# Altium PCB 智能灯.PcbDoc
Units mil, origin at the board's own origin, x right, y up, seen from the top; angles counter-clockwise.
Board outline 3937.01 x 3937.01 mil, 2 copper layers (Top Layer, Bottom Layer); 70 components, 42 nets, 334 pads, 4 vias.
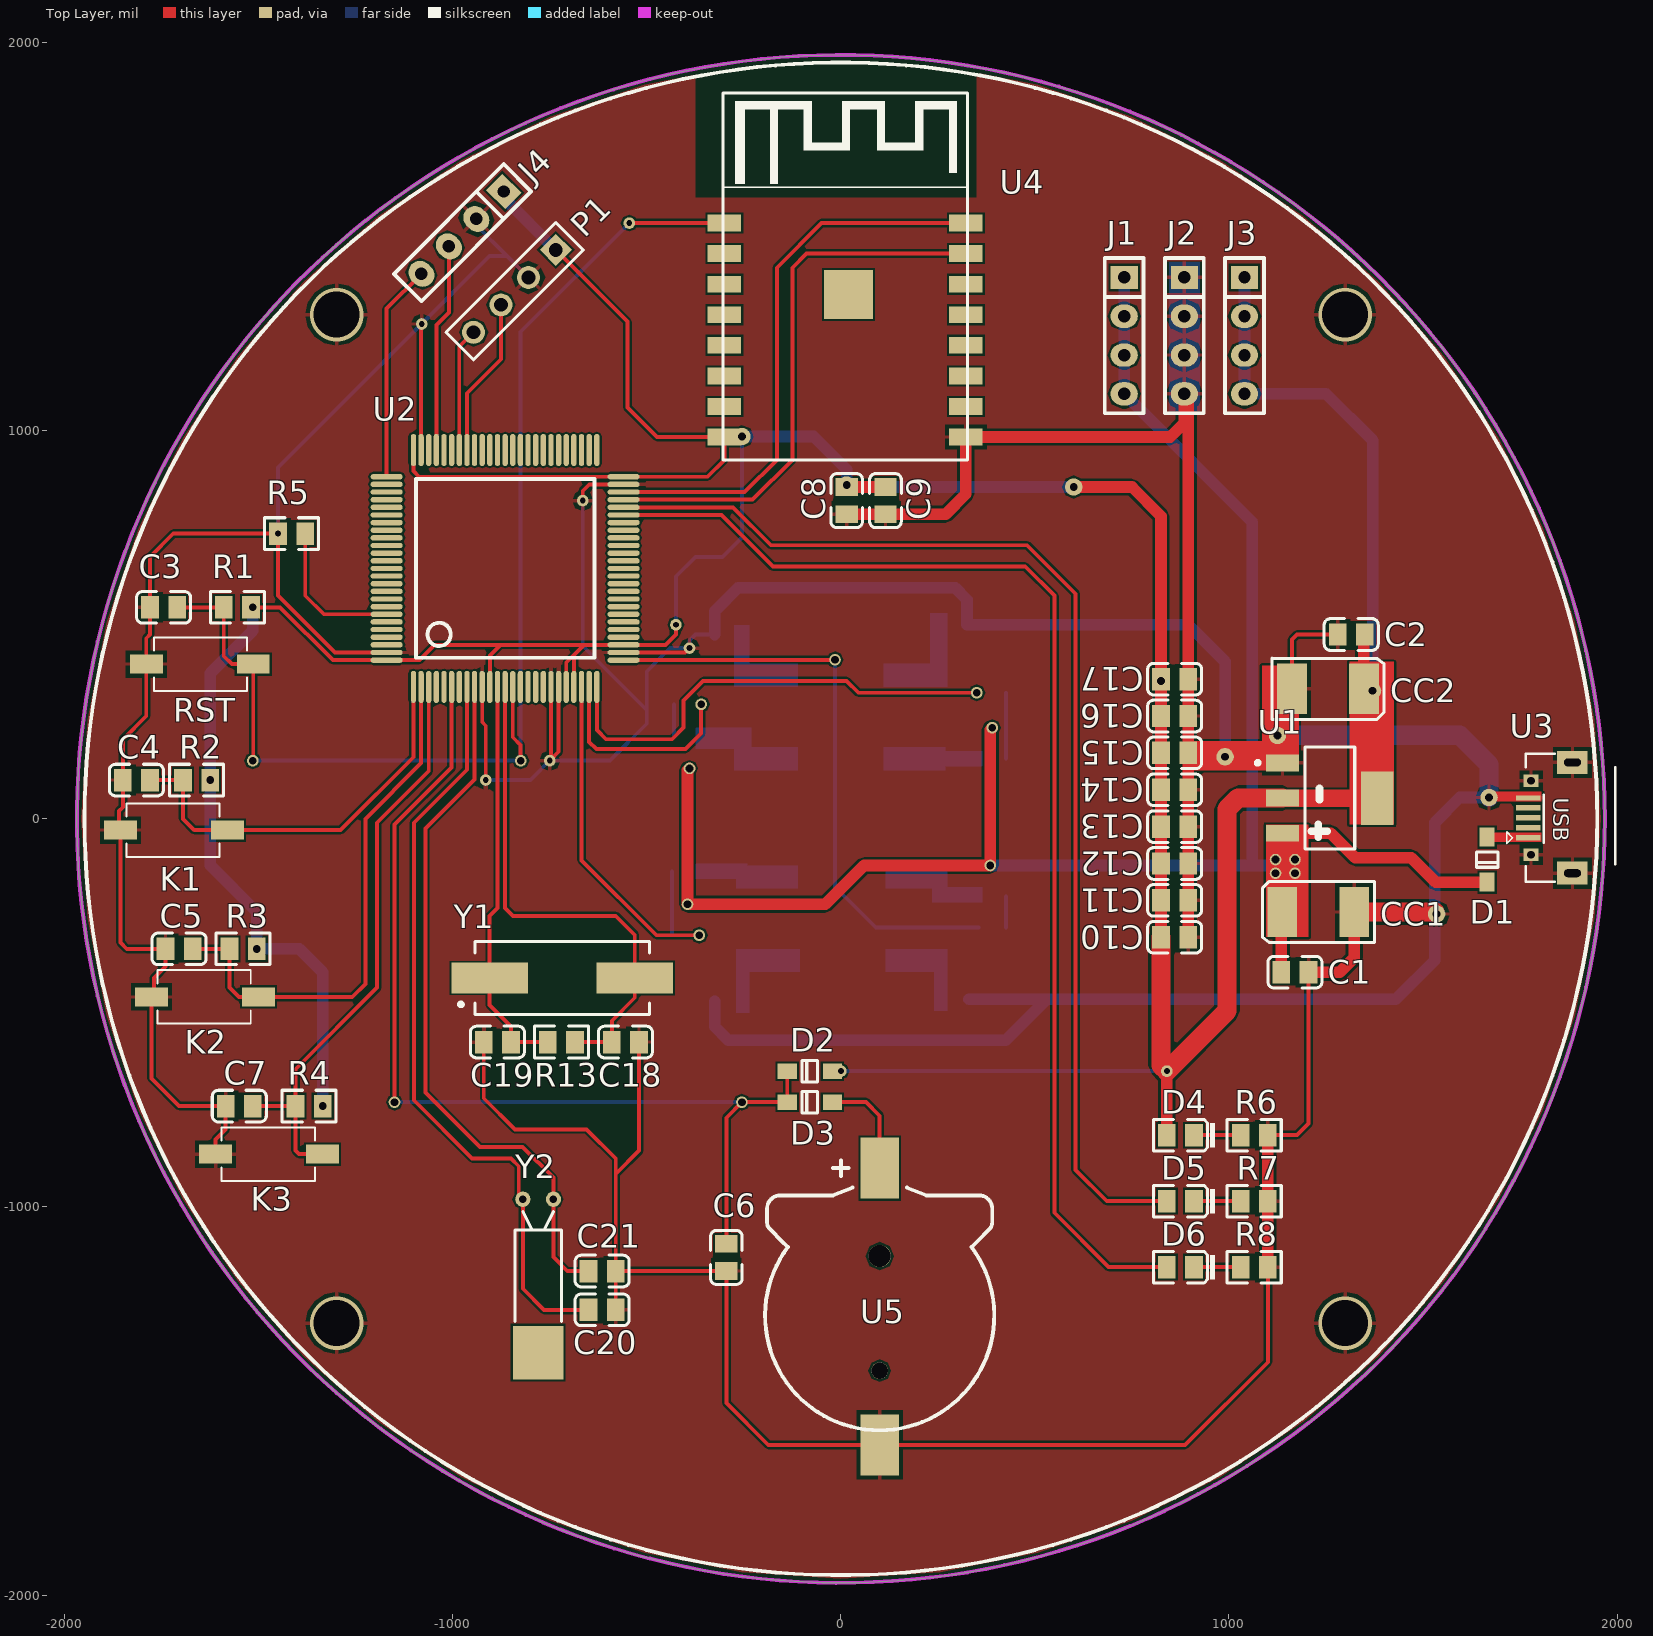
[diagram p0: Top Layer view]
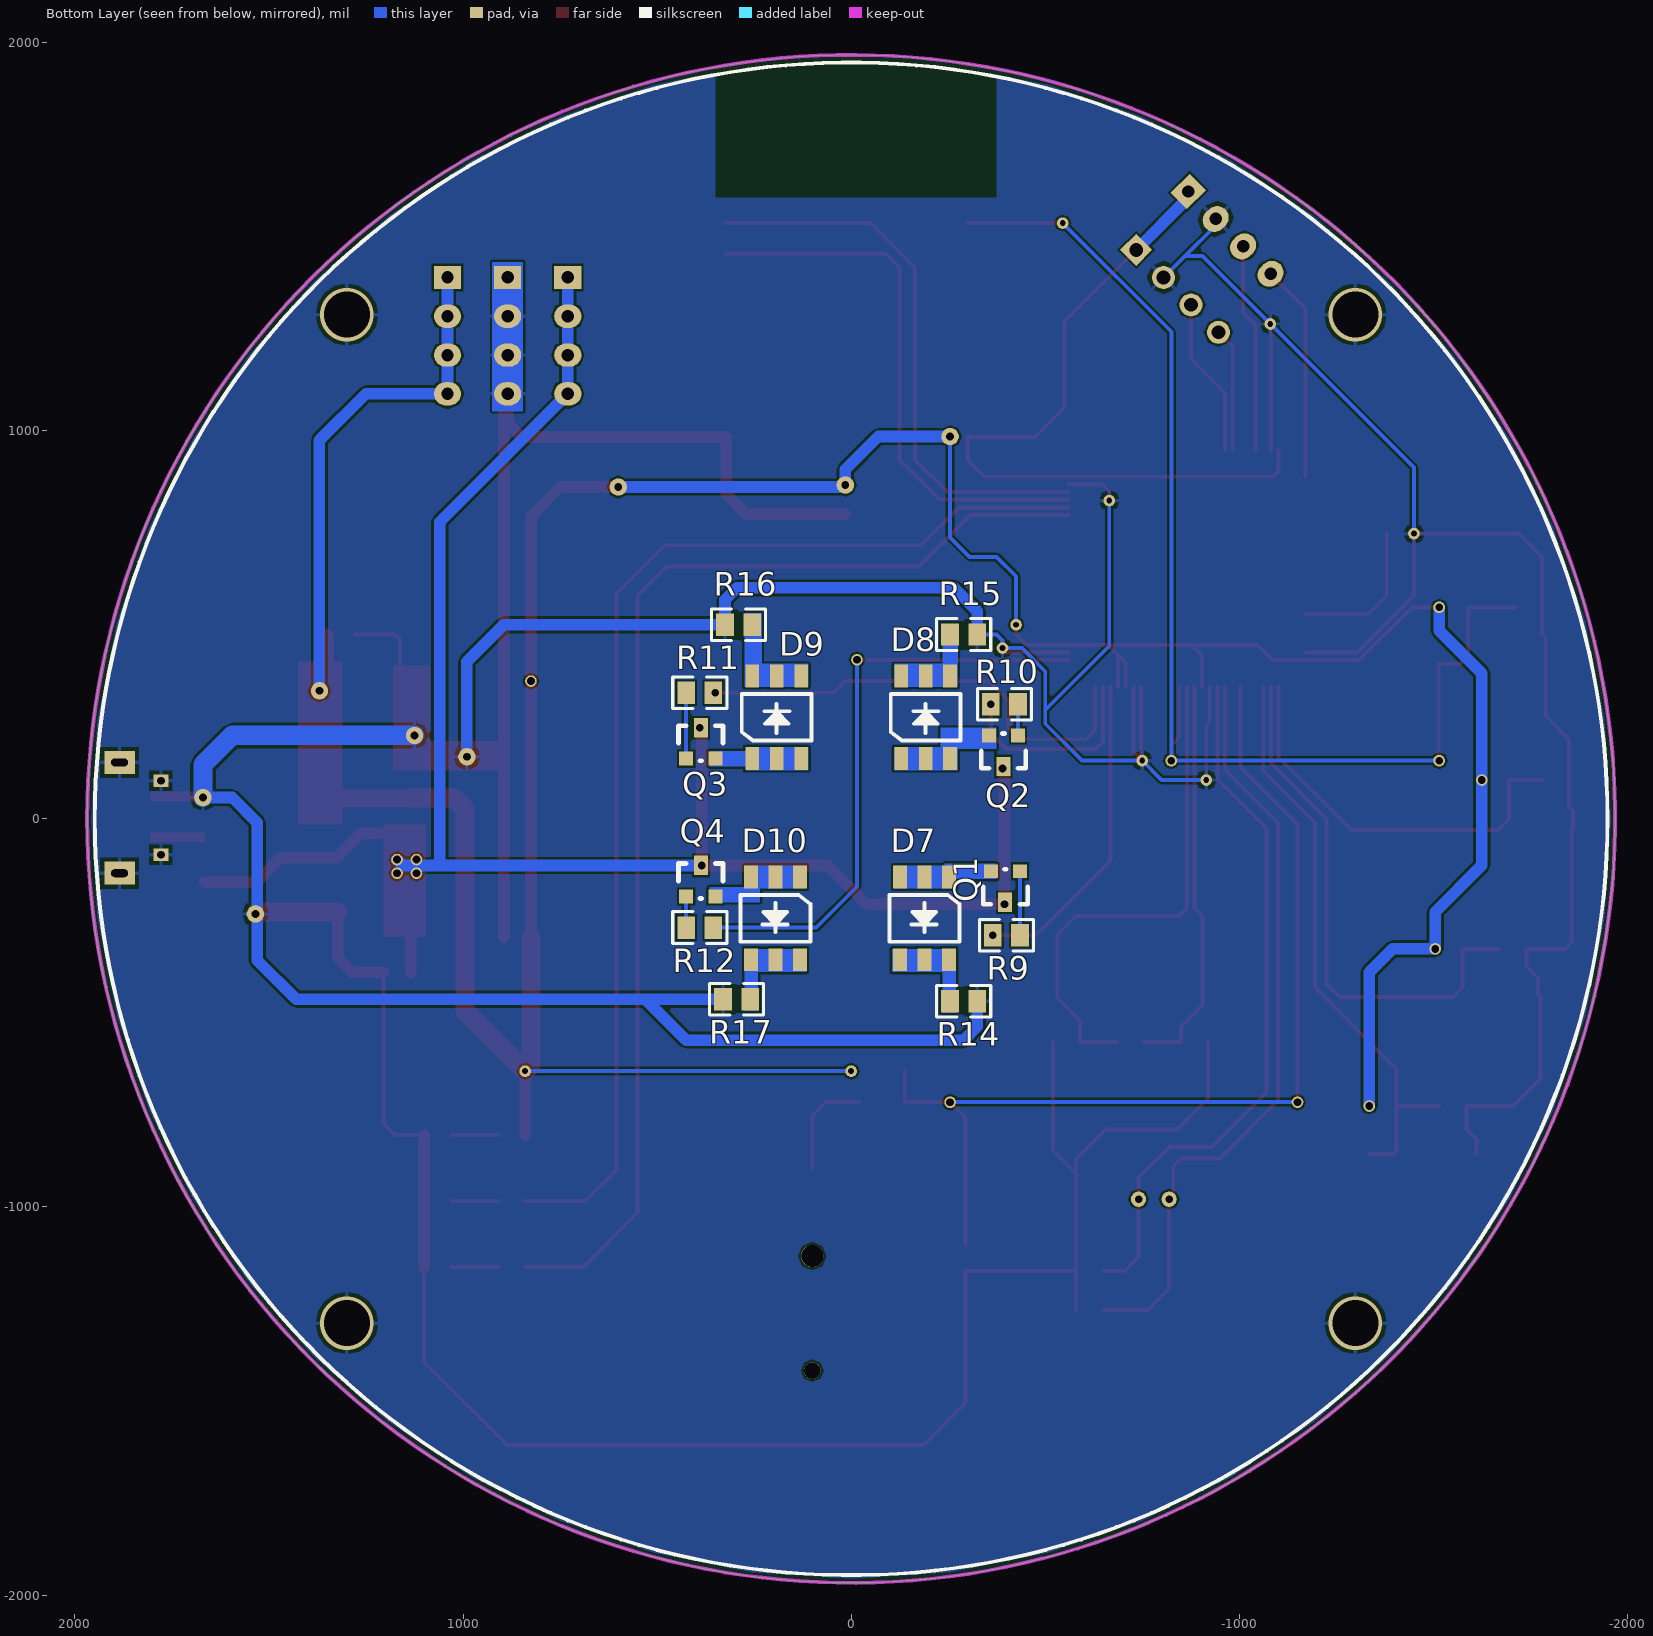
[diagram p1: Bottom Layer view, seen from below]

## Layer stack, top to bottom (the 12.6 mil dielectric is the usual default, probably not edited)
Top Solder: solder mask 0.4, Solder Resist, Dk 3.5
Top Layer: signal copper 1.4
Dielectric 1: dielectric 12.6, FR-4, Dk 4.8
Bottom Layer: signal copper 1.4
Bottom Solder: solder mask 0.4, Solder Resist, Dk 3.5

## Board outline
-1968.5,0 ccw(c0,0) 0,-1968.5 ccw(c0,0) 1968.5,0 ccw(c0,0) 0,1968.5 ccw(c0,0)

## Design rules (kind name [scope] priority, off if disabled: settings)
Clearance [All] p1: gap=5
PolygonConnect [All] p1: connectstyle=Relief reliefconductorwidth=10 reliefentries=4 polygonreliefangle="90 Angle" airgapwidth=10
RoutingVias [All] p1: holewidth=28 width=50 viastyle="Through Hole" minholewidth=28 minwidth=50 maxholewidth=28 maxwidth=50
SolderMaskExpansion [All] p1: expansion=4
Width Width_2 [InNet('VUSB')] p1: maxlimit=50 minlimit=10 preferedwidth=30 minimp=50.000000 maximp=50.000000 favimp=50.000000
Width Width_1 [InNet('VCC3.3')] p2: maxlimit=50 minlimit=10 preferedwidth=10 minimp=50.000000 maximp=50.000000 favimp=50.000000
Width [InNet('GND')] p3: maxlimit=50 minlimit=10 preferedwidth=10 minimp=50.000000 maximp=50.000000 favimp=50.000000
30 further rules are at their usual default settings.

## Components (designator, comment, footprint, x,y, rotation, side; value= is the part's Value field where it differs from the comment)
C1 "104" LC-0805_C 1170,-395 r180 top
C2 "104" LC-0805_C 1315,475 r0 top
C3 "104" LC-0805_C -1745,545 r0 top
C4 "105" LC-0805_C -1815,100 r180 top
C5 "105" LC-0805_C -1705,-335 r180 top
C6 "225" LC-0805_C -295,-1130 r90 top
C7 "105" LC-0805_C -1549.96,-740 r180 top
C8 "10uF" LC-0805_C 15,820 r90 top
C9 "100nF" LC-0805_C 115,820 r90 top
C10 "104" LC-0805_C 860,-305 r180 top
C11 "104" LC-0805_C 860,-210 r180 top
C12 "104" LC-0805_C 860,-115 r180 top
C13 "104" LC-0805_C 860,-20 r180 top
C14 "104" LC-0805_C 860,75 r180 top
C15 "104" LC-0805_C 860,170 r180 top
C16 "104" LC-0805_C 860,265 r180 top
C17 "104" LC-0805_C 860,360 r180 top
C18 "22pF" LC-0805_C -555,-575 r180 top
C19 "22pF" LC-0805_C -885,-575 r180 top
C20 "22pF" LC-0805_C -615,-1265 r180 top
C21 "22pF" LC-0805_C -615,-1165 r0 top
CC1 "Cap Tan C" TAN-C-6032 1230,-240 r180 top
CC2 "Cap Tan C" TAN-C-6032 1255,335 r0 top
D1 "SS14" LC-SOD-123 1665,-105 r90 top
D2 "SS14" LC-SOD-123 -80,-650 r0 top
D3 "SS14" LC-SOD-123 -80,-730 r0 top
D4 "红灯 0805" LC-0805_LED_S1 875,-815 r180 top
D5 "蓝灯 0603" LC-0805_LED_S1 875,-985 r180 top
D6 "蓝灯 0603" LC-0805_LED_S1 875,-1155 r180 top
D7 "LED-5050" LED-5050W -253.86,-151.5 r270 bottom
D8 "LED-5050" LED-5050W -127,156.5 r90 bottom
D9 "LED-5050" LED-5050W 256.86,156.5 r90 bottom
D10 "LED-5050" LED-5050W 130,-151.5 r270 bottom
J1 "Pin HDR1X4" "Pin HDR1X4/2.54mm-S" 730,1395 r0 top
J2 "Pin HDR1X4" "Pin HDR1X4/2.54mm-S" 885,1395 r0 top
J3 "Pin HDR1X4" "Pin HDR1X4/2.54mm-S" 1040,1395 r0 top
J4 "Pin HDR1X4" "Pin HDR1X4/2.54mm-S" -868.58,1616.42 r315 top
K1 "KEY" KEY_2 -1710,-45 r180 top
K2 "KEY" KEY_2 -1630,-475 r180 top
K3 "KEY" KEY_2 -1465,-880 r180 top
P1 "Header 4" HDR1X4 -734.29,1465.71 r225 top
Q1 "NPN" SOT-23 -400,-170 r0 bottom
Q2 "NPN" SOT-23 -395,180 r0 bottom
Q3 "NPN" SOT-23 390,190 r180 bottom
Q4 "NPN" SOT-23 390,-165 r180 bottom
R1 "10KΩ" LC-0805_R -1555,545 r0 top
R2 "10KΩ" LC-0805_R -1660,100 r0 top
R3 "10KΩ" LC-0805_R -1540,-335 r0 top
R4 "10KΩ" LC-0805_R -1370,-740 r0 top
R5 "10KΩ" LC-0805_R -1415,735 r0 top
R6 "47KΩ" LC-0805_R 1065.04,-815 r0 top
R7 "47KΩ" LC-0805_R 1065.04,-985 r0 top
R8 "47KΩ" LC-0805_R 1065.04,-1155 r0 top
R9 "10KΩ" LC-0805_R -400,-300 r0 bottom
R10 "10KΩ" LC-0805_R -395,295 r0 bottom
R11 "10KΩ" LC-0805_R 390,325 r180 bottom
R12 "10KΩ" LC-0805_R 390,-280 r180 bottom
R13 "1MΩ" LC-0805_R -719.96,-575 r0 top
R14 "75Ω" LC-0805_R -290,-470 r180 bottom
R15 "75Ω" LC-0805_R -290,475 r180 bottom
R16 "75Ω" LC-0805_R 290,500 r0 bottom
R17 "75Ω" LC-0805_R 295,-465 r0 bottom
RST "RESET" KEY_2 -1660,415 r0 top
U1 "AMS1117" SOT-223 1265,65 r270 top
U2 "STM32F407VGT6" "LQFP100 14x14" -865,645 r0 top
U3 "USB" USB_B 1845,-122.28 r90 top
U4 "ESP-12S Module" "ESP-12S Module" 11.02,1259.41 r0 top
U5 "BAT" CR1220_A 100,-1280 r90 top
Y1 "8MHz" XTAL-SMD -905,-410 r0 top
Y2 "32.768KHz" OSC-3x8-WI-B -740.63,-980 r180 top

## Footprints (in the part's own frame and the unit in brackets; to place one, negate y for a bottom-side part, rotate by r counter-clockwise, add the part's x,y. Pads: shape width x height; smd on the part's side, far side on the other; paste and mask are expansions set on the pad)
CR1220_A [mm] "纽扣电池座"
  round 1.1 hole 1.1: 0(-3.6,0)
  round 1.45 hole 1.45: 0(3.9,0)
  rect 4x2.5 smd: 1(9.652,0) 2(-8.458,0)
  silkscreen extent -7.5,-7.5 10.16,7.5, body extent -9.42,-7.45 10.34,7.45, height 4.05
"ESP-12S Module" [mm]
  rect 2.2x1.1 smd: 1(-7.9,7) 2(-7.9,5) 3(-7.9,3) 4(-7.9,1) 5(-7.9,-1) 6(-7.9,-3) 7(-7.9,-5) 8(-7.9,-7) 9(7.9,-7) 10(7.9,-5) 11(7.9,-3) 12(7.9,-1) 13(7.9,1) 14(7.9,3) 15(7.9,5) 16(7.9,7)
  rect 3.2x3.2 smd: 17(0.22,2.321)
  silkscreen extent -8,-8.5 8,15.5
HDR1X4 [mm] "Connector; Header; 4 Position"
  rect 1.5x1.5 hole 0.9: 1(0,0)
  round 1.5 hole 0.9: 2(2.54,0) 3(5.08,0) 4(7.62,0)
  silkscreen extent -1.27,-1.27 8.89,1.27, body extent -1.27,-1.27 8.89,1.27, height 7.58
KEY_2 [mil] "贴片"
  rect 85x49.37 smd: 1(-129.57,-16.14) 2(146.02,-16.14)
  silkscreen extent -110,-85 130,53, body extent -110,-88 130,58
LC-0805_C [mm]
  rect 1.16x1.47 smd: 1(-0.89,0) 2(0.89,0)
  silkscreen extent -1.77,-1.04 1.77,1.04, body extent -1,-0.62 1,0.63, height 0.77
LC-0805_LED_S1 [mm]
  rect 1.16x1.47 smd: A(0.89,0) K(-0.89,0)
  silkscreen extent -2.25,-1.04 1.77,1.03, body extent -1.01,-0.62 1.01,0.62, height 1.1
LC-0805_R [mm]
  rect 1.16x1.47 smd: 1(-0.89,0) 2(0.89,0)
  silkscreen extent -1.77,-1.04 1.77,1.03, body extent -1,-0.62 1,0.63, height 0.49
LC-SOD-123 [mm]
  rect 1.25x1 smd: 1(1.475,0) 2(-1.475,0)
  silkscreen extent -0.5,-0.7 0.5,0.7, body extent -1.85,-0.77 1.85,0.78, height 1.35
LED-5050W [mil]
  rect 59.06x35.43 smd: 1(-1.5,-2) 2(211.5,-2) 3(-1.5,-65) 4(211.5,-65) 5(-1.5,-128) 6(211.5,-128)
  silkscreen extent 45,-155 165,25, body extent -1,-162 211,35, height 65
"LQFP100 14x14" [mm]
  oval 0.35x2.1 smd: 1(-6,-7.747) 2(-5.5,-7.747) 3(-5,-7.747) 4(-4.5,-7.747) 5(-4,-7.747) 6(-3.5,-7.747) 7(-3,-7.747) 8(-2.5,-7.747) 9(-2,-7.747) 10(-1.5,-7.747) 11(-1,-7.747) 12(-0.5,-7.747) 13(0,-7.747) 14(0.5,-7.747) 15(1,-7.747) 16(1.5,-7.747) 17(2,-7.747) 18(2.5,-7.747) 19(3,-7.747) 20(3.5,-7.747) 21(4,-7.747) 22(4.5,-7.747) 23(5,-7.747) 24(5.5,-7.747) 25(6,-7.747) 51(6,7.758) 52(5.5,7.758) 53(5,7.758) 54(4.5,7.758) 55(4,7.758) 56(3.5,7.758) 57(3,7.758) 58(2.5,7.758) 59(2,7.758) 60(1.5,7.758) 61(1,7.758) 62(0.5,7.758) 63(0,7.758) 64(-0.5,7.758) 65(-1,7.758) 66(-1.5,7.758) 67(-2,7.758) 68(-2.5,7.758) 69(-3,7.758) 70(-3.5,7.758) 71(-4,7.758) 72(-4.5,7.758) 73(-5,7.758) 74(-5.5,7.758) 75(-6,7.758)
  oval 2.1x0.35 smd: 26(7.752,-5.994) 27(7.752,-5.494) 28(7.752,-4.994) 29(7.752,-4.494) 30(7.752,-3.994) 31(7.752,-3.494) 32(7.752,-2.994) 33(7.752,-2.494) 34(7.752,-1.994) 35(7.752,-1.494) 36(7.752,-0.994) 37(7.752,-0.494) 38(7.752,0.006) 39(7.752,0.506) 40(7.752,1.006) 41(7.752,1.506) 42(7.752,2.006) 43(7.752,2.506) 44(7.752,3.006) 45(7.752,3.506) 46(7.752,4.006) 47(7.752,4.506) 48(7.752,5.006) 49(7.752,5.506) 50(7.752,6.006) 76(-7.752,6.006) 77(-7.752,5.506) 78(-7.752,5.006) 79(-7.752,4.506) 80(-7.752,4.006) 81(-7.752,3.506) 82(-7.752,3.006) 83(-7.752,2.506) 84(-7.752,2.006) 85(-7.752,1.506) 86(-7.752,1.006) 87(-7.752,0.506) 88(-7.752,0.006) 89(-7.752,-0.494) 90(-7.752,-0.994) 91(-7.752,-1.494) 92(-7.752,-1.994) 93(-7.752,-2.494) 94(-7.752,-2.994) 95(-7.752,-3.494) 96(-7.752,-3.994) 97(-7.752,-4.494) 98(-7.752,-4.994) 99(-7.752,-5.494) 100(-7.752,-5.994)
  silkscreen extent -5.84,-5.84 5.84,5.85, body extent -8,-7.98 8,8.03, height 1.45
OSC-3x8-WI-B [mm]
  rect 3.3x3.5 smd: 0(1,10.033)
  round 1 hole 0.5: 1(0,0) 2(2,0)
  silkscreen extent -0.52,0.8 2.52,8, body extent -0.48,-0.13 2.52,10.05, height 3.03
"Pin HDR1X4/2.54mm-S" [mil]
  rect 70x60 hole 32: 1(0,0)
  oval 70x60 hole 32: 2(0,-100) 3(0,-200) 4(0,-300)
  silkscreen extent -50,-350 50,50, body extent -50,-350 50,50, height 336
SOT-23 [mil]
  rect 36x36 smd: B(-35,-35) E(40,-35)
  rect 36x50 smd: C(3,45)
  silkscreen extent -55,-40 60,50, body extent -54,-48 60,62, height 47
SOT-223 [mm] "ASM1117系列"
  rect 1.1x2.15 smd: 1(-2.012,-3.227) 2(0.288,-3.227) 3(2.588,-3.227)
  rect 3.5x2.15 smd: 2(0.288,2.973)
  silkscreen extent -3.06,-4.98 3.64,1.5, body extent -3,-3.48 3.5,3.48, height 1.7
TAN-C-6032 [mm]
  rect 1.95x3.3 smd: 1(-2.35,0) 2(2.35,0)
  silkscreen extent -3.68,-2.01 3.66,2, body extent -3,-1.6 3,1.6, height 2.6
USB_B [mm]
  rect 0.35x1.6 smd: 1(1.875,1.884) 2(2.525,1.884) 3(3.175,1.884) 4(3.825,1.884) 5(4.475,1.884)
  rect 1.5x2 hole 0.5 slot 1.1 at 90 deg: 5(-0.45,-1.016) 5(6.8,-1.016)
  rect 0.8x1 hole 0.5: 5(0.75,1.694) 5(5.6,1.694)
  silkscreen extent -1.02,-3.81 7.37,3.28, body extent -0.83,-3.73 7.18,1.87, height 2.8
XTAL-SMD [mm]
  rect 5x2 smd: 1(0,0) 2(9.5,0)
  silkscreen extent -2,-2.4 10.45,2.4, body extent -1.95,-2.46 11.45,2.44, height 4

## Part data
C1 C2 C4 C5 C6 C7 C8 C9 C10 C11 C12 C13 C14 C15 C16 C17: library part "0805 6.8nF (682) 10% 50V", "贴片电容"
C3: library part "0805 330nF (334) 10% 50V", "贴片电容"
C18 C19 C20 C21: library part "0805 6pF (6R0) 0.25pF 50V", "贴片电容"
CC1 CC2: "Polarized Capacitor (Radial)"
D1 D2 D3: library part D
D4: library part "0805 红灯", "发光二极管"
D5 D6: library part "0603 蓝灯", "发光二极管"
K1 K2 K3: "微动开关"
P1: "Header, 4-Pin"
Q1 Q2 Q3 Q4: "NPN三极管"
R1 R13: library part "0805 390KΩ (3903) 1%", "贴片电阻"
R2 R3 R4 R6 R7 R8 R9 R10 R11 R12: library part "0805 11KΩ (1102) 1%", "贴片电阻"
R5: library part "0805 1.8KΩ (1801) 1%", "贴片电阻"
R14 R15 R16 R17: library part "0805 1.2KΩ (1201) 1%", "贴片电阻"
RST: library part KEY, "微动开关"
U1: "3.3V电压转换器AMS1117"
U2: library part STM32F103VBT6
U5: "纽扣电池座CR1220"
Y1 Y2: library part XTAL, "晶体振荡器"

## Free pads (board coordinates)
  round 30 hole 20: 2(-1625,100) 2(-1515,150) 2(-1515,545) 2(-1505,-335) 2(-1334.96,-740) 2(-1150,-730) 2(-825,150) 2(-395,-220) 2(-390,130) 2(-365,-300) 2(-360,295) 2(-255,-730) 2(-15,410) 2(350,325) 2(385,-120) 2(390,235) 2(825,355) 2(1120,-140) 2(1120,-105) 2(1170,-140) 2(1170,-105)
  round 30 hole 15: 2(-1450.04,735) 2(-1080,1275) 2(-915,100) 2(-750,150) 2(-665,820) 2(-545,1535) 2(-425,500) 2(-390,440) 2(0,-650) 2(840,-650)
  round 45 hole 20: 2(-255,985) 2(15,860) 2(600,855) 2(990,160) 2(1125,215) 2(1370,330) 2(1535,-245) 2(1670,55)

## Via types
v1: diameter 137.8, hole 118.11, Top Layer to Bottom Layer, 4 vias

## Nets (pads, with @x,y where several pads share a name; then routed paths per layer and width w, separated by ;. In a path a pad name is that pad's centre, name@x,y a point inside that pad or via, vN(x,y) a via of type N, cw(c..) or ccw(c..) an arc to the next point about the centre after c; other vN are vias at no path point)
DS1: pad.2@-365,-300 R9.2 U2.23 | length 830
  Top Layer w10: U2.23 -668.15,-106.85 -475,-300 pad.2@-365,-300
DS2: pad.2@-360,295 R10.2 U2.24 | length 529.2
  Top Layer w10: U2.24 -648.46,198.46 -630,180 -400,180 -360,220 pad.2@-360,295
DS3: pad.2@350,325 R11.2 U2.25 | length 1215.4
  Top Layer w10: U2.25 -628.78,228.78 -605,205 -435,205 -405,235 -405,305 -355,355 15,355 45,325 pad.2@350,325
DS4: pad.2@-15,410 R12.2 U2.26 | length 1543.2
  Top Layer w10: U2.26 pad.2@-15,409
  Bottom Layer w10: pad.2@-15,410 -15,-175 90,-280 R12.2
GND: C1.1 C2.1 C3.1 C4.2 C5.2 C6.1 C7.2 C8.1 C9.1 C10.1 C11.1 C12.1 C13.1 C14.1 C15.1 C16.1 C17.1 C18.1 C19.2 C20.1 C21.2 CC1.1 CC2.1 J2.1 J2.2 J2.3 J2.4 J4.2 K1.2 K2.2 K3.2 P1.2 pad.2@990,160 pad.2@1125,215 pad.2@1535,-245 pad.2@1670,55 pad.2@-390,440 pad.2@-665,820 pad.2@-750,150 pad.2@-915,100 pad.2@-1080,1275 pad.2@-1450.04,735 R5.1 R6.2 R7.2 R8.2 R14.2 R15.2 R16.2 R17.2 RST.1 U1.1 U2.10 U2.19 U2.20 U2.27 U2.49 U2.74 U2.99 U3.5 U4.9 U5.2 | length 19575.1
  Top Layer w10: K3.2 -1611.02,-826.02 -1585,-800 C7.2 -1705,-740 -1776.02,-668.98 K2.2 -1770,-452.83 -1770,-410 -1740.04,-380.04 C5.2 -1840,-335 -1856.02,-318.98 K1.2 -1860,-24.88 -1860,20 -1850.04,29.96 C4.2 -1850.04,204.96 -1789.57,265.43 RST.1 -1789.57,465.43 -1780.04,474.96 C3.1 -1780.04,674.96 -1720,735 R5.1 -1450.04,575.04 -1303.69,428.69 U2.99 ; U2.74 -1081.54,1273.46 pad.2@-1080,1275 ; U2.10 -924.06,249.06 -915,240 pad.2@-915,100 ; C19.2 -920.04,-719.96 -840,-800 -655,-800 -579.96,-875.04 -579.96,-914.96 ; pad.2@-750,150 pad.2@-746.89,153.11 ; U2.19 pad.2@-746.89,153.11 ; U2.20 -727.2,172.8 pad.2@-746.89,153.11 ; pad.2@-665,820 -665,845 -648.24,861.76 U2.49 ; C20.1 C21.2 ; U2.27 -401.31,428.69 pad.2@-390,440 ; C18.1 -519.96,-854.96 -579.96,-914.96 ; R8.2 1100.08,-1399.92 887,-1613 U5.2 -187,-1613 -295,-1505 C6.1 C6.1 C21.2 ; R6.2 1175,-815 1205.04,-784.96 C1.1 ; CC2.1 1162.48,462.48 1175,475 C2.1 ; C21.2 -579.96,-914.96
  Top Layer w30: C8.1 C9.1 269.96,784.96 322.05,837.05 U4.9 848.82,983.82 885,1020 J2.4 895.04,1084.96 C17.1 C16.1 C15.1 C14.1 C13.1 C12.1 C11.1 C10.1 ; R8.2 R7.2 R6.2 ; C1.1 1285,-395 1322.52,-357.48 CC1.1 ; pad.2@1530,-240 pad.2@1535,-245
  Top Layer w50: CC1.1 pad.2@1530,-240
  Bottom Layer w10: pad.2@-1450.04,735 -1450.04,904.96 -1080,1275 -905,1450 -860,1450 ; J4.2 -939.29,1529.29 -860,1450 ; pad.2@-915,100 -800,100 -750,150 -595,150 -500,245 -500,280 ; P1.2 -860,1450 ; pad.2@-665,820 -665,445 -500,280 ; R15.2 -375,475 -390,460 -390,440 -440,440 -500,380 -500,280
  Bottom Layer w30: R14.2 -325.04,-534.96 -290,-570 425,-570 530,-465 ; R15.2 -325.04,534.96 -265,595 295,595 325.04,564.96 R16.2 895,500 990,405 pad.2@990,160 ; R17.2 530,-465 ; pad.2@1670,55 1595,55 1530,-10 1530,-365 1430,-465 530,-465
  Bottom Layer w50: pad.2@1125,215 1595,215 1670,140 pad.2@1670,55
  other v1: -1299.21,-1299.21 1299.21,-1299.21 -1299.21,1299.21 1299.21,1299.21
KEY1: C4.1 K1.1 R2.1 U2.1 | length 1049.6
  Top Layer w10: C4.1 R2.1 -1695.04,0.04 -1666.14,-28.86 K1.1 -1288.86,-28.86 -1101.22,158.78 U2.1
KEY2: C5.1 K2.1 R3.1 U2.2 | length 1393.3
  Top Layer w10: C5.1 R3.1 -1575.04,-434.96 -1551.14,-458.86 K2.1 -1258.86,-458.86 -1225,-425 -1225,0 -1081.54,143.46 U2.2
KEY3: C7.1 K3.1 R4.1 U2.3 | length 1520.3
  Top Layer w10: C7.1 R4.1 ; K3.1 -1396.14,-863.86 -1405.04,-854.96 R4.1 ; U2.3 -1061.85,123.15 -1195,-10 -1195,-435 -1405.04,-645.04 R4.1
LED1: D5.A U2.46 | length 3010.1
  Top Layer w10: U2.46 -277.7,802.7 -180,705 480,705 605,580 605,-905 685,-985 D5.A
LED2: D6.A U2.45 | length 3133.9
  Top Layer w10: U2.45 -308.02,783.02 -175,650 475,650 550,575 550,-1015 690,-1155 D6.A
NetD1_1: D1.1 U3.1
NetD3_1: D3.1 U5.1 | length 271.4
  Top Layer w10: D3.1 65,-730 100,-765 U5.1
NetD4_K: D4.K R6.1 | length 120
  Top Layer w10: D4.K R6.1
NetD5_K: D5.K R7.1 | length 120
  Top Layer w10: D5.K R7.1
NetD6_K: D6.K R8.1 | length 120
  Top Layer w10: D6.K R8.1
NetD7_1: D7.1 D7.3 D7.5 Q1.E
NetD7_2: D7.2 D7.4 D7.6 R14.1
NetD8_1: D8.1 D8.3 D8.5 Q2.E
NetD8_2: D8.2 D8.4 D8.6 R15.1
NetD9_1: D9.1 D9.3 D9.5 Q3.E
NetD9_2: D9.2 D9.4 D9.6 R16.1
NetD10_1: D10.1 D10.3 D10.5 Q4.E
NetD10_2: D10.2 D10.4 D10.6 R17.1
NetQ1_B: Q1.B R9.1 | length 165
  Bottom Layer w10: R9.1 R9.1 Q1.B
NetQ2_B: Q2.B R10.1 | length 80
  Bottom Layer w10: R10.1 Q2.B Q2.B
NetQ3_B: Q3.B R11.1 | length 170
  Bottom Layer w10: Q3.B Q3.B R11.1
NetQ4_B: Q4.B R12.1 | length 80
  Bottom Layer w10: Q4.B R12.1 R12.1
NetR5_2: R5.2 U2.94 | length 389.6
  Top Layer w10: R5.2 -1379.96,574.96 -1332.11,527.11 U2.94
NRST: C3.2 pad.2@-545,1535 pad.2@-825,150 pad.2@-1515,150 R1.1 RST.2 U2.14 U4.1 | length 3213.4
  Top Layer w10: C3.2 R1.1 -1590.04,420.04 -1568.86,398.86 RST.2 -1513.98,151.02 pad.2@-1515,150 ; U2.14 -845.31,210.31 -825,190 pad.2@-825,150 ; pad.2@-545,1535 U4.1
  Bottom Layer w10: pad.2@-1515,150 -825,150 -825,1255 pad.2@-545,1535
OSC32_IN: C20.2 U2.8 Y2.2 | length 1973.9
  Top Layer w10: U2.8 -963.43,126.57 -1100,-10 -1100,-725 -950,-875 -850,-875 -830,-895 -830,-969.37 Y2.2 -819.37,-1210.63 -765,-1265 C20.2
OSC32_OUT: C21.1 U2.9 Y2.1 | length 1828.2
  Top Layer w10: U2.9 -943.74,101.89 -943.43,101.57 -1070,-25 -1070,-705 -930,-845 -820,-845 -740.63,-924.37 Y2.1 -740.63,-1129.37 -705,-1165 C21.1
OSC_IN: C19.1 R13.1 U2.12 Y1.1 | length 1041.2
  Top Layer w10: U2.12 -884.69,-229.69 -905,-250 Y1.1 -905,-480 -849.96,-535.04 C19.1 R13.1
OSC_OUT: C18.2 R13.2 U2.13 Y1.2 | length 1327.9
  Top Layer w10: U2.13 -865,-230 -845,-250 -580,-250 -530.99,-299.01 Y1.2 -530.99,-460.99 -590.04,-520.04 C18.2 R13.2
SWCLK: J4.4 U2.76 | length 559.9
  Top Layer w10: U2.76 -1170.21,1314.79 J4.4
SWDIO: J4.3 U2.72 | length 537.9
  Top Layer w10: U2.72 -1042.17,1272.83 -1010,1305 J4.3
U1_RX: P1.4 U2.69 | length 318.3
  Top Layer w10: U2.69 -983.11,1216.89 P1.4
U1_TX: P1.3 U2.68 | length 410.2
  Top Layer w10: U2.68 -963.43,1096.57 -875.71,1184.29 P1.3
U3_RX: U2.48 U4.16 | length 1458.8
  Top Layer w10: U2.48 -247.93,842.07 -165,925 -165,1420 -50,1535 U4.16
U3_TX: U2.47 U4.15 | length 1434.4
  Top Layer w10: U2.47 -227.61,822.39 -125,925 -125,1420 -88.74,1456.26 U4.15
VBAT: C6.2 D2.2 D3.2 pad.2@-255,-730 pad.2@-1150,-730 U2.6 | length 2589.4
  Top Layer w10: pad.2@-1150,-730 -1150,-15 -1002.8,132.2 U2.6 ; C6.2 -295,-770 -255,-730 D3.2 D2.2
  Bottom Layer w10: -1135,-730 pad.2@-255,-730
VCC3.3: C2.2 C8.2 C9.2 C10.2 C11.2 C12.2 C13.2 C14.2 C15.2 C16.2 C17.2 CC2.2 D2.1 D4.A J3.1 J3.2 J3.3 J3.4 J4.1 P1.1 pad.2@0,-650 pad.2@15,860 pad.2@600,855 pad.2@825,355 pad.2@840,-650 pad.2@1370,330 pad.2@-255,985 pad.2@-425,500 pad.2@-1334.96,-740 pad.2@-1505,-335 pad.2@-1515,545 pad.2@-1625,100 R1.2 R2.2 R3.2 R4.2 U1.2 U2.11 U2.21 U2.22 U2.28 U2.50 U2.75 U2.100 U4.8 | length 11642.3
  Top Layer w10: R1.2 -1445,545 -1309,409 U2.100 -1086,409 -1046.63,448.37 -876.63,448.37 ; U2.75 -1101.22,896.22 -1086.44,881.44 U2.50 -343.56,881.44 -300,925 U4.8 -473.82,983.82 -550,1060 -550,1281.42 P1.1 ; U2.11 -904.37,420.63 -876.63,448.37 ; U2.21 -707.52,402.48 -687.83,422.17 ; U2.22 -687.83,422.17 ; pad.2@-425,500 -425,475 -451.63,448.37 U2.28 -661.63,448.37 ; -876.63,448.37 -661.63,448.37 ; -687.83,422.17 -661.63,448.37
  Top Layer w30: C8.2 C9.2 ; pad.2@600,855 750,855 824.96,780.04 C17.2 C16.2 C15.2 C14.2 C13.2 C12.2 C11.2 C10.2 ; D4.A 839.96,-650.04 pad.2@840,-650 ; CC2.2 1347.52,472.48 C2.2
  Top Layer w50: C10.2 824.96,-635.04 pad.2@839.96,-650.04 ; pad.2@840,-650 995,-495 995,25 1023.66,53.66 U1.2@1137.95,53.66
  Bottom Layer w10: pad.2@-425,500 -425,625 -375,675 -305,675 -255,725 pad.2@-255,985 ; pad.2@0,-650 pad.2@840,-650
  Bottom Layer w30: pad.2@-1515,545 -1515,485 -1625,375 -1625,100 -1625,-120 -1505,-240 -1505,-335 -1395,-335 -1334.96,-395.04 pad.2@-1334.96,-740 ; J4.1 -868.58,1600 P1.1 ; pad.2@-255,985 -70,985 15,900 15,860 20,855 pad.2@600,855 ; J3.1 J3.2 J3.3 J3.4 1250,1095 1370,975 pad.2@1370,330
VUSB: C1.2 CC1.2 D1.2 J1.1 J1.2 J1.3 J1.4 pad.2@385,-120 pad.2@390,235 pad.2@1120,-105 pad.2@1120,-140 pad.2@1170,-105 pad.2@1170,-140 pad.2@-390,130 pad.2@-395,-220 Q1.C Q2.C Q3.C Q4.C U1.3 | length 4910.1
  Top Layer w30: pad.2@-390,130 -395,125 -395,-220 -40,-220 60,-120 385,-120 385,230 pad.2@390,235 ; C1.2 1134.96,-242.52 CC1.2 1137.48,-37.36 U1.3 1261.89,-36.89 1325,-100 1470,-100 1533.07,-163.07 D1.2
  Bottom Layer w30: Q4.C 1060,-120 ; J1.1 J1.2 J1.3 J1.4 1060,765 1060,-120 ; pad.2@1170,-105 1155,-120 1060,-120
pads on no net: U2.4 U2.5 U2.7 U2.15 U2.16 U2.17 U2.18 U2.29 U2.30 U2.31 U2.32 U2.33 U2.34 U2.35 U2.36 U2.37 U2.38 U2.39 U2.40 U2.41 U2.42 U2.43 U2.44 U2.51 U2.52 U2.53 U2.54 U2.55 U2.56 U2.57 U2.58 U2.59 U2.60 U2.61 U2.62 U2.63 U2.64 U2.65 U2.66 U2.67 U2.70 U2.71 U2.73 U2.77 U2.78 U2.79 U2.80 U2.81 U2.82 U2.83 U2.84 U2.85 U2.86 U2.87 U2.88 U2.89 U2.90 U2.91 U2.92 U2.93 U2.95 U2.96 U2.97 U2.98 U3.2 U3.3 U3.4 U4.2 U4.3 U4.4 U4.5 U4.6 U4.7 U4.10 U4.11 U4.12 U4.13 U4.14 U4.17 U5.0 Y2.0

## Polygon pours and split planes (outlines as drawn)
GND on Top Layer "NONET_L-01_P-001" (solid, remove dead copper, pour order 0): -1230,1540 -1400,1370 -1420,1370 -1438.63,1343.63 -1495,1275 -1570,1185 -1700,985 -1745,915 -1815.62,760.62 -1870,615 -1895,532.9 -1940,330 -1947.2,288.84 -1965,95 -1965,-115 -1913.23,-463.23 -1895,-535 -1831.05,-698.95 -1790,-815 -1745,-911.03 -1675,-1035 -1640,-1095 -1495,-1280 -1325.4,-1455.44 -1142.26,-1607.22 -1105,-1630 -917.6,-1744.58 -815,-1790 -719.02,-1832.49 -620,-1870 -535.82,-1894.18 -370,-1935 -325.24,-1941.45 -137.48,-1968.5 50,-1970 400.48,-1930.94 490,-1905 640.48,-1861.4 760,-1815 872.36,-1764.65 1020,-1680 1078.55,-1646.74 1345,-1440 1513.47,-1258.73 1530,-1235 1659.69,-1064.83 1700,-990 1776.36,-848.26 1825,-730 1870.46,-613.51 1925,-420 1931.42,-380.28 1965,10 1931.42,380.28 1920,450 1860.39,643.4 1810,780 1756.67,888.32 1635,1100 1604.87,1139.91 1360,1425 1078.55,1653.55 1005,1695 860.65,1776.36 785,1810 710.87,1842.97 625,1870 560.59,1886.99 465,1915 400.49,1927.33 210,1960 205,1965 -160,1965 -410.36,1931.17 -480,1910 -644.95,1859.85 -750,1820 -848.26,1776.36 -970,1715
GND on Bottom Layer "NONET_L-01_P-001" (solid, remove dead copper, pour order 4): 5,1970 0.54,1965.54 -74.8,1965.54 -164.46,1965.54 -170,1960 -195,1960 -270,1950 -320,1940 -345,1940 -365.93,1933.03 -425,1925 -475,1910 -495,1910 -510.32,1901.2 -555,1895 -574.35,1882.85 -595,1880 -610.47,1871.45 -640,1865 -658.77,1855 -670,1855 -691.19,1843.17 -710,1835 -740.69,1820.69 -765,1815 -795.31,1800.69 -830,1790 -854.9,1774.9 -900,1750 -930.07,1734.93 -950,1725 -965,1725 -985,1705 -1010,1680 -1025,1680 -1040,1680 -1055,1665 -1075,1645 -1085,1645 -1100,1645 -1120,1625 -1140,1605 -1155,1605 -1175,1585 -1195,1565 -1200,1565 -1205,1565 -1230,1540 -1270,1500 -1280,1500 -1285,1500 -1360,1425 -1480,1305 -1515,1250 -1540,1220 -1555,1205 -1629.39,1104.58 -1650,1075 -1710.06,975.04 -1735,930 -1777.4,852.4 -1795,810 -1825.98,735.39 -1850,675 -1874.76,600.24 -1905,500 -1915.19,455.04 -1935,350 -1945.5,300.08 -1965,160 -1970,155 -1970,-75 -1935,-350 -1925,-405 -1874.85,-599.95 -1840,-695 -1809.6,-774.83 -1775,-850 -1717.7,-961.51 -1605,-1140 -1575.63,-1180 -1345,-1440 -1190.51,-1567.71 -1165,-1585 -1015.73,-1686.21 -970,-1715 -841.93,-1775.36 -760,-1815 -708.33,-1840 -640,-1860 -580,-1881.12 -475,-1910 -425,-1925 -285,-1950 -264.41,-1950.66 5,-1968.5 276.64,-1950 292.01,-1950 310,-1945 375.07,-1935.25 405,-1925 499.16,-1904.16 555,-1885 644.52,-1860 700,-1840 756.9,-1817.17 810,-1795 850.36,-1775.36 915,-1745 939.82,-1729.67 995,-1695 1034.75,-1674.6 1130,-1610 1167.38,-1585 1325,-1460 1575.63,-1180 1600,-1140 1659.1,-1059.43 1675,-1030 1733.19,-933.19 1765,-870 1797.67,-797.67 1830,-720 1852.04,-667.04 1880,-565 1899.95,-514.95 1920,-435 1929.5,-389.9 1960,-170 1960,220 1955,225 1920,434.29 1910,485 1864.97,629.99 1835,720 1781.79,836.79 1695,1000 1659.1,1059.43 1490,1285 1290,1485 1290,1495 1045,1668.23 970,1715 795.31,1800.69 670,1850 485,1910 249.69,1952.6 24.28,1965.54

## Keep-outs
Keep-Out Layer:
  circle w10: c0,0 r1968.5

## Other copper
Top Layer:
  rectangle net NetD1_1: 1665,-60 1805,-35
  rectangle net VUSB: 1095,-305 1205,-15
  rectangle net VCC3.3: 1095,30 1425,75
  rectangle net VCC3.3: 1310,-15 1425,405
  rectangle net GND: 1085,125 1180,395
  rectangle net GND: 1660,45 1805,70
  rectangle net GND: 880,125 1180,200
  pour cut-out: -375,1910 -375,1600 350,1600 350,1915 295,1925 40,1950 -209.74,1938.49 -230,1935
Bottom Layer:
  rectangle net NetD8_1: -375,180 -230,235
  rectangle net NetD7_1: -375,-155 -240,-115
  rectangle net NetD10_1: 235,-215 365,-175
  rectangle net GND: 845,1050 925,1435
  rectangle net NetD9_1: 110,125 270,185
  rectangle net NetD9_1: 240,135 365,175
  rectangle net NetD9_2: 110,340 275,400
  rectangle net NetD9_2: 230,340 275,530
  rectangle net NetD10_2: 115,-395 275,-335
  rectangle net NetD10_1: 115,-180 275,-120
  rectangle net NetD7_1: -270,-180 -110,-120
  rectangle net NetD7_2: -270,-395 -105,-335
  rectangle net NetD8_1: -275,125 -110,185
  rectangle net NetD8_2: -270,340 -110,400
  rectangle net NetD10_2: 240,-495 275,-335
  rectangle net NetD7_2: -270,-500 -235,-335
  rectangle net NetD8_2: -275,340 -235,500
  pour cut-out: -375,1930 -375,1600 350,1600 350,1940 279.79,1948.52 234.93,1954.43 30,1968.5 -179.59,1962.57 -195,1960

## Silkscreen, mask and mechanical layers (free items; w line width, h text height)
Top Overlay:
  circle w10: c0,0 r1948.82
Bottom Overlay:
  circle w10: c0,0 r1948.82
